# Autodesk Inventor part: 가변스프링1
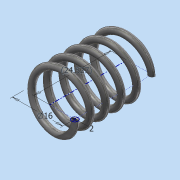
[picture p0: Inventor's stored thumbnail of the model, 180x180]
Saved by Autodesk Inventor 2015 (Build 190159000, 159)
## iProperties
Created: 2018-10
Part Number: 가변스프링1
Material: 스테인레스 스틸
Document SubType Name: Modeling
Designer: SCD-A03
Density: 8 g/cm^3
Appearance: 반연마
Mass: 6.20708 g
Surface Area: 15.7732 cm^2
Volume: 0.775884 cm^3
Author: SCD-A03
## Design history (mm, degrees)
sketch "스케치1"
  geometry: L1 (0, 0)-(8, 0); L2 (8, 0)-(8, 24.527); L3 (8, 24.527)-(0, 24.527); L4 (0, 24.527)-(0, 0); C1 r 1 at (8, 0)
  constraints: 8 end point, 2 parallel, 1 centre point, 1 coincident, 1 horizontal, 1 perpendicular
  dimensions: "d0" = 24.52728 distance of L3.end L1.start (derived); "d1" = 16 diameter of L2 L4; "d2" = 2 diameter of C1
feature "코일1" pitch "d3" = 10; turns "d5" = 5; dims "d4" = 24.52728 (= d0), "d6" = 0, angle "d7" = 90 deg, angle "d8" = 90 deg, "d9" = 0, "d10" = 0
node "작업 평면1"
node "작업 평면2"
sketch "스케치2"
  geometry: L1 (9, 0)-(7, 0) reference; 1 further point
  constraints: 1 horizontal alignment
extrude "돌출1" cut sketch "스케치2" distance "d11" = 10; taper "d12" = 0 deg
sketch "스케치3"
  geometry: L1 (7, 0)-(9, 0) reference; 1 further point
  constraints: 1 horizontal alignment
extrude "돌출2" cut sketch "스케치3" distance "d13" = 10; taper "d14" = 0 deg
node "솔리드1"
node "절단 모서리 투영1"
node "절단 모서리 투영2"
